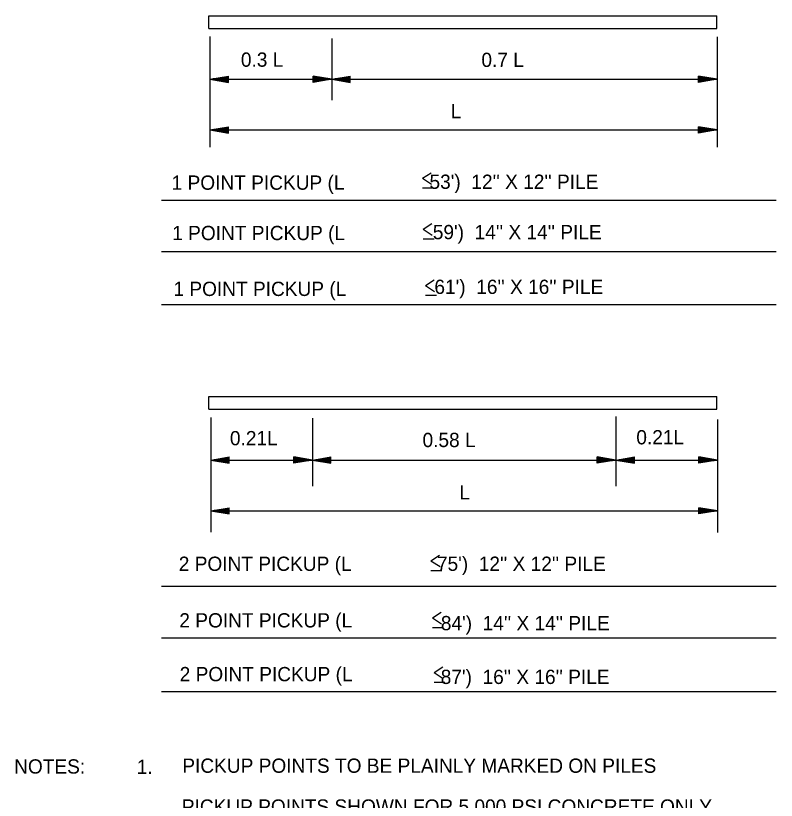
# Model space of a CAD drawing. Extents: x 22369.62 to 22373.29, y 22369.62 to 22372.46.
# Drawn here: x 22372.212 to 22372.836, y 22371.084 to 22371.728 of the extents above; entities that cross this region are included whole.
import ezdxf

# ---------------------------------------------------------------- set-up
doc = ezdxf.new("R2010")
doc.units = 0
for name, color, linetype in [('Level 10', 7, 'Continuous'), ('Level 4', 7, 'Continuous'), ('Level 7', 7, 'Continuous'), ('S-ANNO-DIMS', 7, 'Continuous')]:
    doc.layers.add(name, color=color, linetype=linetype)

msp = doc.modelspace()

# ---------------------------------------------------------------- linework, layer by layer
at = {"layer": 'Level 10'}
for p, q in [((22372.33178, 22371.57674), (22372.83582, 22371.57674)), ((22372.33178, 22371.53446), (22372.83582, 22371.53446)), ((22372.33178, 22371.49102), (22372.83582, 22371.49102)), ((22372.33178, 22371.25995), (22372.83582, 22371.25995)), ((22372.33178, 22371.21767), (22372.83582, 22371.21767)), ((22372.33178, 22371.17358), (22372.83582, 22371.17358))]:
    msp.add_line(p, q, dxfattribs=at)
at = {"layer": 'Level 7'}
for p, q in [((22372.37062, 22371.72793), (22372.78712, 22371.72793)), ((22372.37062, 22371.71751), (22372.37062, 22371.72793)), ((22372.78712, 22371.71751), (22372.78712, 22371.72793)), ((22372.37062, 22371.71751), (22372.78712, 22371.71751)), ((22372.37062, 22371.41555), (22372.78712, 22371.41555)), ((22372.37062, 22371.40513), (22372.37062, 22371.41555)), ((22372.78712, 22371.40513), (22372.78712, 22371.41555)), ((22372.37062, 22371.40513), (22372.78712, 22371.40513))]:
    msp.add_line(p, q, dxfattribs=at)
at = {"layer": 'S-ANNO-DIMS'}
for p, q in [((22372.37145, 22371.71092), (22372.37145, 22371.61999)), ((22372.47141, 22371.70935), (22372.47141, 22371.65875)), ((22372.7873, 22371.71066), (22372.7873, 22371.62012)), ((22372.37145, 22371.67586), (22372.38668, 22371.67845)), ((22372.37145, 22371.67586), (22372.7873, 22371.67586)), ((22372.37145, 22371.67586), (22372.38668, 22371.67586)), ((22372.37145, 22371.67586), (22372.38668, 22371.67327)), ((22372.37424, 22371.67607), (22372.38602, 22371.67807)), ((22372.38637, 22371.67622), (22372.37424, 22371.67607)), ((22372.38637, 22371.67549), (22372.37424, 22371.67563)), ((22372.37424, 22371.67563), (22372.38602, 22371.67364)), ((22372.37759, 22371.67638), (22372.38566, 22371.67772)), ((22372.386, 22371.67653), (22372.37759, 22371.67638)), ((22372.37759, 22371.67532), (22372.38566, 22371.67399)), ((22372.386, 22371.67518), (22372.37759, 22371.67532)), ((22372.38084, 22371.67666), (22372.38535, 22371.67734)), ((22372.38565, 22371.67681), (22372.38084, 22371.67666)), ((22372.38084, 22371.67505), (22372.38535, 22371.67436)), ((22372.38565, 22371.67491), (22372.38084, 22371.67505)), ((22372.38535, 22371.67699), (22372.38394, 22371.67693)), ((22372.38535, 22371.67734), (22372.38535, 22371.67699)), ((22372.38566, 22371.67772), (22372.38565, 22371.67681)), ((22372.38602, 22371.67807), (22372.386, 22371.67653)), ((22372.38602, 22371.67364), (22372.386, 22371.67518)), ((22372.38635, 22371.67807), (22372.38637, 22371.67622)), ((22372.38635, 22371.67364), (22372.38637, 22371.67549)), ((22372.38668, 22371.67327), (22372.38668, 22371.67845)), ((22372.45617, 22371.67327), (22372.45617, 22371.67845)), ((22372.47141, 22371.67586), (22372.45617, 22371.67845)), ((22372.47141, 22371.67586), (22372.45617, 22371.67586)), ((22372.47141, 22371.67586), (22372.45617, 22371.67327)), ((22372.45649, 22371.67807), (22372.45649, 22371.67622)), ((22372.45649, 22371.67622), (22372.46862, 22371.67607)), ((22372.45649, 22371.67549), (22372.46862, 22371.67563)), ((22372.45649, 22371.67364), (22372.45649, 22371.67549)), ((22372.46862, 22371.67607), (22372.45684, 22371.67807)), ((22372.45684, 22371.67807), (22372.45686, 22371.67653)), ((22372.46862, 22371.67563), (22372.45684, 22371.67364)), ((22372.45684, 22371.67364), (22372.45686, 22371.67518)), ((22372.45686, 22371.67653), (22372.46527, 22371.67638)), ((22372.45686, 22371.67518), (22372.46527, 22371.67532)), ((22372.46527, 22371.67638), (22372.4572, 22371.67772)), ((22372.4572, 22371.67772), (22372.4572, 22371.67681)), ((22372.4572, 22371.67681), (22372.46203, 22371.67666)), ((22372.46527, 22371.67532), (22372.4572, 22371.67399)), ((22372.4572, 22371.67491), (22372.46203, 22371.67505)), ((22372.45752, 22371.67734), (22372.4575, 22371.67699)), ((22372.4575, 22371.67699), (22372.4589, 22371.67693)), ((22372.46203, 22371.67666), (22372.45752, 22371.67734)), ((22372.46203, 22371.67505), (22372.45752, 22371.67436)), ((22372.47141, 22371.67586), (22372.48664, 22371.67845)), ((22372.47141, 22371.67586), (22372.48664, 22371.67586)), ((22372.47141, 22371.67586), (22372.48664, 22371.67327)), ((22372.4742, 22371.67607), (22372.48597, 22371.67807)), ((22372.48633, 22371.67622), (22372.4742, 22371.67607)), ((22372.48633, 22371.67549), (22372.4742, 22371.67563)), ((22372.4742, 22371.67563), (22372.48597, 22371.67364)), ((22372.47755, 22371.67638), (22372.48562, 22371.67772)), ((22372.48596, 22371.67653), (22372.47755, 22371.67638)), ((22372.47755, 22371.67532), (22372.48562, 22371.67399)), ((22372.48596, 22371.67518), (22372.47755, 22371.67532)), ((22372.4808, 22371.67666), (22372.48531, 22371.67734)), ((22372.48561, 22371.67681), (22372.4808, 22371.67666)), ((22372.4808, 22371.67505), (22372.48531, 22371.67436)), ((22372.48561, 22371.67491), (22372.4808, 22371.67505)), ((22372.48531, 22371.67699), (22372.48391, 22371.67693)), ((22372.48531, 22371.67734), (22372.48531, 22371.67699)), ((22372.48562, 22371.67772), (22372.48561, 22371.67681)), ((22372.48597, 22371.67807), (22372.48596, 22371.67653)), ((22372.48597, 22371.67364), (22372.48596, 22371.67518)), ((22372.48631, 22371.67807), (22372.48633, 22371.67622)), ((22372.48631, 22371.67364), (22372.48633, 22371.67549)), ((22372.48664, 22371.67327), (22372.48664, 22371.67845)), ((22372.77206, 22371.67327), (22372.77206, 22371.67845)), ((22372.7873, 22371.67586), (22372.77206, 22371.67845)), ((22372.7873, 22371.67586), (22372.77206, 22371.67586)), ((22372.7873, 22371.67586), (22372.77206, 22371.67327)), ((22372.77239, 22371.67807), (22372.77237, 22371.67622)), ((22372.77237, 22371.67622), (22372.7845, 22371.67607)), ((22372.77237, 22371.67549), (22372.7845, 22371.67563)), ((22372.77239, 22371.67364), (22372.77237, 22371.67549)), ((22372.7845, 22371.67607), (22372.77272, 22371.67807)), ((22372.77272, 22371.67807), (22372.77273, 22371.67653)), ((22372.7845, 22371.67563), (22372.77272, 22371.67364)), ((22372.77272, 22371.67364), (22372.77273, 22371.67518)), ((22372.77273, 22371.67653), (22372.78114, 22371.67638)), ((22372.77273, 22371.67518), (22372.78114, 22371.67532)), ((22372.78114, 22371.67638), (22372.77308, 22371.67772)), ((22372.77308, 22371.67772), (22372.77309, 22371.67681)), ((22372.78114, 22371.67532), (22372.77308, 22371.67399)), ((22372.77309, 22371.67681), (22372.7779, 22371.67666)), ((22372.77309, 22371.67491), (22372.7779, 22371.67505)), ((22372.7734, 22371.67734), (22372.77339, 22371.67699)), ((22372.77339, 22371.67699), (22372.77479, 22371.67693)), ((22372.7779, 22371.67666), (22372.7734, 22371.67734)), ((22372.7779, 22371.67505), (22372.7734, 22371.67436)), ((22372.38535, 22371.67472), (22372.38394, 22371.67478)), ((22372.38535, 22371.67436), (22372.38535, 22371.67472)), ((22372.38566, 22371.67399), (22372.38565, 22371.67491)), ((22372.4572, 22371.67399), (22372.4572, 22371.67491)), ((22372.4575, 22371.67472), (22372.4589, 22371.67478)), ((22372.45752, 22371.67436), (22372.4575, 22371.67472)), ((22372.48531, 22371.67472), (22372.48391, 22371.67478)), ((22372.48531, 22371.67436), (22372.48531, 22371.67472)), ((22372.48562, 22371.67399), (22372.48561, 22371.67491)), ((22372.77308, 22371.67399), (22372.77309, 22371.67491)), ((22372.77339, 22371.67472), (22372.77479, 22371.67478)), ((22372.7734, 22371.67436), (22372.77339, 22371.67472)), ((22372.37145, 22371.63421), (22372.38668, 22371.63679)), ((22372.37424, 22371.63443), (22372.38602, 22371.63642)), ((22372.38602, 22371.63642), (22372.386, 22371.63488)), ((22372.38635, 22371.63642), (22372.38637, 22371.63457)), ((22372.38668, 22371.63162), (22372.38668, 22371.63679)), ((22372.77206, 22371.63162), (22372.77206, 22371.63679)), ((22372.7873, 22371.63421), (22372.77206, 22371.63679)), ((22372.77239, 22371.63642), (22372.77237, 22371.63457)), ((22372.7845, 22371.63443), (22372.77272, 22371.63642)), ((22372.77272, 22371.63642), (22372.77273, 22371.63488)), ((22372.37145, 22371.63421), (22372.7873, 22371.63421)), ((22372.37145, 22371.63421), (22372.38668, 22371.63421)), ((22372.37145, 22371.63421), (22372.38668, 22371.63162)), ((22372.38637, 22371.63457), (22372.37424, 22371.63443)), ((22372.38637, 22371.63384), (22372.37424, 22371.63399)), ((22372.37424, 22371.63399), (22372.38602, 22371.632)), ((22372.37759, 22371.63474), (22372.38566, 22371.63607)), ((22372.386, 22371.63488), (22372.37759, 22371.63474)), ((22372.37759, 22371.63368), (22372.38566, 22371.63234)), ((22372.386, 22371.63353), (22372.37759, 22371.63368)), ((22372.38084, 22371.63501), (22372.38535, 22371.6357)), ((22372.38565, 22371.63516), (22372.38084, 22371.63501)), ((22372.38084, 22371.63341), (22372.38535, 22371.63272)), ((22372.38565, 22371.63325), (22372.38084, 22371.63341)), ((22372.38535, 22371.63534), (22372.38394, 22371.63528)), ((22372.38535, 22371.63307), (22372.38394, 22371.63313)), ((22372.38535, 22371.6357), (22372.38535, 22371.63534)), ((22372.38535, 22371.63272), (22372.38535, 22371.63307)), ((22372.38566, 22371.63607), (22372.38565, 22371.63516)), ((22372.38566, 22371.63234), (22372.38565, 22371.63325)), ((22372.38602, 22371.632), (22372.386, 22371.63353)), ((22372.38635, 22371.632), (22372.38637, 22371.63384)), ((22372.7873, 22371.63421), (22372.77206, 22371.63421)), ((22372.7873, 22371.63421), (22372.77206, 22371.63162)), ((22372.77237, 22371.63457), (22372.7845, 22371.63443)), ((22372.77237, 22371.63384), (22372.7845, 22371.63399)), ((22372.77239, 22371.632), (22372.77237, 22371.63384)), ((22372.7845, 22371.63399), (22372.77272, 22371.632)), ((22372.77272, 22371.632), (22372.77273, 22371.63353)), ((22372.77273, 22371.63488), (22372.78114, 22371.63474)), ((22372.77273, 22371.63353), (22372.78114, 22371.63368)), ((22372.78114, 22371.63474), (22372.77308, 22371.63607)), ((22372.77308, 22371.63607), (22372.77309, 22371.63516)), ((22372.78114, 22371.63368), (22372.77308, 22371.63234)), ((22372.77308, 22371.63234), (22372.77309, 22371.63325)), ((22372.77309, 22371.63516), (22372.7779, 22371.63501)), ((22372.77309, 22371.63325), (22372.7779, 22371.63341)), ((22372.7734, 22371.6357), (22372.77339, 22371.63534)), ((22372.77339, 22371.63534), (22372.77479, 22371.63528)), ((22372.77339, 22371.63307), (22372.77479, 22371.63313)), ((22372.7734, 22371.63272), (22372.77339, 22371.63307)), ((22372.7779, 22371.63501), (22372.7734, 22371.6357)), ((22372.7779, 22371.63341), (22372.7734, 22371.63272)), ((22372.5458, 22371.59454), (22372.55288, 22371.59914)), ((22372.5458, 22371.59454), (22372.55322, 22371.58972)), ((22372.5458, 22371.58663), (22372.55466, 22371.58663)), ((22372.54643, 22371.5528), (22372.55352, 22371.5574)), ((22372.54643, 22371.5528), (22372.55385, 22371.54798)), ((22372.54643, 22371.5449), (22372.55529, 22371.5449)), ((22372.54833, 22371.50664), (22372.55541, 22371.51124)), ((22372.54833, 22371.50664), (22372.55574, 22371.50182)), ((22372.54833, 22371.49873), (22372.55719, 22371.49873)), ((22372.37221, 22371.39844), (22372.37221, 22371.30436)), ((22372.70424, 22371.39932), (22372.70424, 22371.3421)), ((22372.45552, 22371.39782), (22372.45552, 22371.34217)), ((22372.78755, 22371.39673), (22372.78755, 22371.30403)), ((22372.37221, 22371.36349), (22372.38745, 22371.36607)), ((22372.38745, 22371.36089), (22372.38745, 22371.36607)), ((22372.44028, 22371.36089), (22372.44028, 22371.36607)), ((22372.45552, 22371.36349), (22372.44028, 22371.36607)), ((22372.45552, 22371.36349), (22372.47075, 22371.36607)), ((22372.47075, 22371.36089), (22372.47075, 22371.36607)), ((22372.68902, 22371.36089), (22372.68902, 22371.36607)), ((22372.70424, 22371.36349), (22372.68902, 22371.36607)), ((22372.70424, 22371.36349), (22372.71948, 22371.36607)), ((22372.71948, 22371.36089), (22372.71948, 22371.36607)), ((22372.77232, 22371.36089), (22372.77232, 22371.36607)), ((22372.78755, 22371.36349), (22372.77232, 22371.36607)), ((22372.37221, 22371.36349), (22372.78755, 22371.36349)), ((22372.37221, 22371.36349), (22372.38745, 22371.36349)), ((22372.37221, 22371.36349), (22372.38745, 22371.36089)), ((22372.375, 22371.3637), (22372.38679, 22371.3657)), ((22372.38713, 22371.36384), (22372.375, 22371.3637)), ((22372.38713, 22371.36311), (22372.375, 22371.36326)), ((22372.375, 22371.36326), (22372.38679, 22371.36127)), ((22372.37836, 22371.36401), (22372.38643, 22371.36534)), ((22372.38677, 22371.36416), (22372.37836, 22371.36401)), ((22372.37836, 22371.36295), (22372.38643, 22371.36161)), ((22372.38677, 22371.3628), (22372.37836, 22371.36295)), ((22372.3816, 22371.36428), (22372.38611, 22371.36497)), ((22372.38642, 22371.36444), (22372.3816, 22371.36428)), ((22372.3816, 22371.36268), (22372.38611, 22371.36199)), ((22372.38642, 22371.36253), (22372.3816, 22371.36268)), ((22372.38612, 22371.36461), (22372.38472, 22371.36455)), ((22372.38612, 22371.36234), (22372.38472, 22371.36241)), ((22372.38611, 22371.36497), (22372.38612, 22371.36461)), ((22372.38611, 22371.36199), (22372.38612, 22371.36234)), ((22372.38643, 22371.36534), (22372.38642, 22371.36444)), ((22372.38643, 22371.36161), (22372.38642, 22371.36253)), ((22372.38679, 22371.3657), (22372.38677, 22371.36416)), ((22372.38679, 22371.36127), (22372.38677, 22371.3628)), ((22372.38712, 22371.3657), (22372.38713, 22371.36384)), ((22372.38712, 22371.36127), (22372.38713, 22371.36311)), ((22372.45552, 22371.36349), (22372.44028, 22371.36349)), ((22372.45552, 22371.36349), (22372.44028, 22371.36089)), ((22372.44061, 22371.3657), (22372.4406, 22371.36384)), ((22372.4406, 22371.36384), (22372.45272, 22371.3637)), ((22372.4406, 22371.36311), (22372.45272, 22371.36326)), ((22372.44061, 22371.36127), (22372.4406, 22371.36311)), ((22372.45272, 22371.3637), (22372.44094, 22371.3657)), ((22372.44094, 22371.3657), (22372.44096, 22371.36416)), ((22372.45272, 22371.36326), (22372.44094, 22371.36127)), ((22372.44094, 22371.36127), (22372.44096, 22371.3628)), ((22372.44096, 22371.36416), (22372.44937, 22371.36401)), ((22372.44096, 22371.3628), (22372.44937, 22371.36295)), ((22372.44937, 22371.36401), (22372.44131, 22371.36534)), ((22372.44131, 22371.36534), (22372.44132, 22371.36444)), ((22372.44937, 22371.36295), (22372.44131, 22371.36161)), ((22372.44131, 22371.36161), (22372.44132, 22371.36253)), ((22372.44132, 22371.36444), (22372.44613, 22371.36428)), ((22372.44132, 22371.36253), (22372.44613, 22371.36268)), ((22372.44162, 22371.36497), (22372.44161, 22371.36461)), ((22372.44161, 22371.36461), (22372.44302, 22371.36455)), ((22372.44161, 22371.36234), (22372.44302, 22371.36241)), ((22372.44162, 22371.36199), (22372.44161, 22371.36234)), ((22372.44613, 22371.36428), (22372.44162, 22371.36497)), ((22372.44613, 22371.36268), (22372.44162, 22371.36199)), ((22372.45552, 22371.36349), (22372.47075, 22371.36349)), ((22372.45552, 22371.36349), (22372.47075, 22371.36089)), ((22372.45831, 22371.3637), (22372.47009, 22371.3657)), ((22372.47043, 22371.36384), (22372.45831, 22371.3637)), ((22372.47043, 22371.36311), (22372.45831, 22371.36326)), ((22372.45831, 22371.36326), (22372.47009, 22371.36127)), ((22372.46166, 22371.36401), (22372.46972, 22371.36534)), ((22372.47007, 22371.36416), (22372.46166, 22371.36401)), ((22372.46166, 22371.36295), (22372.46972, 22371.36161)), ((22372.47007, 22371.3628), (22372.46166, 22371.36295)), ((22372.4649, 22371.36428), (22372.46941, 22371.36497)), ((22372.46971, 22371.36444), (22372.4649, 22371.36428)), ((22372.4649, 22371.36268), (22372.46941, 22371.36199)), ((22372.46971, 22371.36253), (22372.4649, 22371.36268)), ((22372.46942, 22371.36461), (22372.46802, 22371.36455)), ((22372.46942, 22371.36234), (22372.46802, 22371.36241)), ((22372.46941, 22371.36497), (22372.46942, 22371.36461)), ((22372.46941, 22371.36199), (22372.46942, 22371.36234)), ((22372.46972, 22371.36534), (22372.46971, 22371.36444)), ((22372.46972, 22371.36161), (22372.46971, 22371.36253)), ((22372.47009, 22371.3657), (22372.47007, 22371.36416)), ((22372.47009, 22371.36127), (22372.47007, 22371.3628)), ((22372.47042, 22371.3657), (22372.47043, 22371.36384)), ((22372.47042, 22371.36127), (22372.47043, 22371.36311)), ((22372.70424, 22371.36349), (22372.68902, 22371.36349)), ((22372.70424, 22371.36349), (22372.68902, 22371.36089)), ((22372.68934, 22371.3657), (22372.68932, 22371.36384)), ((22372.68932, 22371.36384), (22372.70146, 22371.3637)), ((22372.68932, 22371.36311), (22372.70146, 22371.36326)), ((22372.68934, 22371.36127), (22372.68932, 22371.36311)), ((22372.70146, 22371.3637), (22372.68968, 22371.3657)), ((22372.68968, 22371.3657), (22372.68969, 22371.36416)), ((22372.70146, 22371.36326), (22372.68968, 22371.36127)), ((22372.68968, 22371.36127), (22372.68969, 22371.3628)), ((22372.68969, 22371.36416), (22372.6981, 22371.36401)), ((22372.68969, 22371.3628), (22372.6981, 22371.36295)), ((22372.6981, 22371.36401), (22372.69004, 22371.36534)), ((22372.69004, 22371.36534), (22372.69005, 22371.36444)), ((22372.6981, 22371.36295), (22372.69004, 22371.36161)), ((22372.69004, 22371.36161), (22372.69005, 22371.36253)), ((22372.69005, 22371.36444), (22372.69485, 22371.36428)), ((22372.69005, 22371.36253), (22372.69485, 22371.36268)), ((22372.69485, 22371.36428), (22372.69035, 22371.36497)), ((22372.69035, 22371.36497), (22372.69035, 22371.36461)), ((22372.69035, 22371.36461), (22372.69174, 22371.36455)), ((22372.69485, 22371.36268), (22372.69035, 22371.36199)), ((22372.69035, 22371.36234), (22372.69174, 22371.36241)), ((22372.69035, 22371.36199), (22372.69035, 22371.36234)), ((22372.70424, 22371.36349), (22372.71948, 22371.36349)), ((22372.70424, 22371.36349), (22372.71948, 22371.36089)), ((22372.70704, 22371.3637), (22372.71882, 22371.3657)), ((22372.71917, 22371.36384), (22372.70704, 22371.3637)), ((22372.71917, 22371.36311), (22372.70704, 22371.36326)), ((22372.70704, 22371.36326), (22372.71882, 22371.36127)), ((22372.71039, 22371.36401), (22372.71846, 22371.36534)), ((22372.71881, 22371.36416), (22372.71039, 22371.36401)), ((22372.71039, 22371.36295), (22372.71846, 22371.36161)), ((22372.71881, 22371.3628), (22372.71039, 22371.36295)), ((22372.71364, 22371.36428), (22372.71814, 22371.36497)), ((22372.71845, 22371.36444), (22372.71364, 22371.36428)), ((22372.71364, 22371.36268), (22372.71814, 22371.36199)), ((22372.71845, 22371.36253), (22372.71364, 22371.36268)), ((22372.71814, 22371.36461), (22372.71674, 22371.36455)), ((22372.71814, 22371.36234), (22372.71674, 22371.36241)), ((22372.71814, 22371.36497), (22372.71814, 22371.36461)), ((22372.71814, 22371.36199), (22372.71814, 22371.36234)), ((22372.71846, 22371.36534), (22372.71845, 22371.36444)), ((22372.71846, 22371.36161), (22372.71845, 22371.36253)), ((22372.71882, 22371.3657), (22372.71881, 22371.36416)), ((22372.71882, 22371.36127), (22372.71881, 22371.3628)), ((22372.71915, 22371.3657), (22372.71917, 22371.36384)), ((22372.71915, 22371.36127), (22372.71917, 22371.36311)), ((22372.78755, 22371.36349), (22372.77232, 22371.36349)), ((22372.78755, 22371.36349), (22372.77232, 22371.36089)), ((22372.77264, 22371.3657), (22372.77262, 22371.36384)), ((22372.77262, 22371.36384), (22372.78475, 22371.3637)), ((22372.77262, 22371.36311), (22372.78475, 22371.36326)), ((22372.77264, 22371.36127), (22372.77262, 22371.36311)), ((22372.78475, 22371.3637), (22372.77298, 22371.3657)), ((22372.77298, 22371.3657), (22372.77298, 22371.36416)), ((22372.77298, 22371.36416), (22372.7814, 22371.36401)), ((22372.78475, 22371.36326), (22372.77298, 22371.36127)), ((22372.77298, 22371.3628), (22372.7814, 22371.36295)), ((22372.77298, 22371.36127), (22372.77298, 22371.3628)), ((22372.7814, 22371.36401), (22372.77334, 22371.36534)), ((22372.77334, 22371.36534), (22372.77335, 22371.36444)), ((22372.7814, 22371.36295), (22372.77334, 22371.36161)), ((22372.77334, 22371.36161), (22372.77335, 22371.36253)), ((22372.77335, 22371.36444), (22372.77815, 22371.36428)), ((22372.77335, 22371.36253), (22372.77815, 22371.36268)), ((22372.77815, 22371.36428), (22372.77365, 22371.36497)), ((22372.77365, 22371.36497), (22372.77365, 22371.36461)), ((22372.77365, 22371.36461), (22372.77505, 22371.36455)), ((22372.77815, 22371.36268), (22372.77365, 22371.36199)), ((22372.77365, 22371.36234), (22372.77505, 22371.36241)), ((22372.77365, 22371.36199), (22372.77365, 22371.36234)), ((22372.37221, 22371.32183), (22372.38745, 22371.32442)), ((22372.37221, 22371.32183), (22372.78755, 22371.32183)), ((22372.37221, 22371.32183), (22372.38745, 22371.32183)), ((22372.37221, 22371.32183), (22372.38745, 22371.31925)), ((22372.375, 22371.32205), (22372.38679, 22371.32404)), ((22372.38713, 22371.3222), (22372.375, 22371.32205)), ((22372.38713, 22371.32147), (22372.375, 22371.32161)), ((22372.375, 22371.32161), (22372.38679, 22371.31962)), ((22372.37836, 22371.32236), (22372.38643, 22371.3237)), ((22372.38677, 22371.32251), (22372.37836, 22371.32236)), ((22372.37836, 22371.3213), (22372.38643, 22371.31997)), ((22372.38677, 22371.32116), (22372.37836, 22371.3213)), ((22372.3816, 22371.32263), (22372.38611, 22371.32332)), ((22372.38642, 22371.32278), (22372.3816, 22371.32263)), ((22372.3816, 22371.32103), (22372.38611, 22371.32034)), ((22372.38642, 22371.32087), (22372.3816, 22371.32103)), ((22372.38612, 22371.32297), (22372.38472, 22371.32291)), ((22372.38611, 22371.32332), (22372.38612, 22371.32297)), ((22372.38643, 22371.3237), (22372.38642, 22371.32278)), ((22372.38679, 22371.32404), (22372.38677, 22371.32251)), ((22372.38679, 22371.31962), (22372.38677, 22371.32116)), ((22372.38712, 22371.32404), (22372.38713, 22371.3222)), ((22372.38712, 22371.31962), (22372.38713, 22371.32147)), ((22372.38745, 22371.31925), (22372.38745, 22371.32442)), ((22372.77232, 22371.31925), (22372.77232, 22371.32442)), ((22372.78755, 22371.32183), (22372.77232, 22371.32442)), ((22372.78755, 22371.32183), (22372.77232, 22371.32183)), ((22372.78755, 22371.32183), (22372.77232, 22371.31925)), ((22372.77264, 22371.32404), (22372.77262, 22371.3222)), ((22372.77262, 22371.3222), (22372.78475, 22371.32205)), ((22372.77262, 22371.32147), (22372.78475, 22371.32161)), ((22372.77264, 22371.31962), (22372.77262, 22371.32147)), ((22372.78475, 22371.32205), (22372.77298, 22371.32404)), ((22372.77298, 22371.32404), (22372.77298, 22371.32251)), ((22372.77298, 22371.32251), (22372.7814, 22371.32236)), ((22372.78475, 22371.32161), (22372.77298, 22371.31962)), ((22372.77298, 22371.32116), (22372.7814, 22371.3213)), ((22372.77298, 22371.31962), (22372.77298, 22371.32116)), ((22372.7814, 22371.32236), (22372.77334, 22371.3237)), ((22372.77334, 22371.3237), (22372.77335, 22371.32278)), ((22372.7814, 22371.3213), (22372.77334, 22371.31997)), ((22372.77335, 22371.32278), (22372.77815, 22371.32263)), ((22372.77335, 22371.32087), (22372.77815, 22371.32103)), ((22372.77815, 22371.32263), (22372.77365, 22371.32332)), ((22372.77365, 22371.32332), (22372.77365, 22371.32297)), ((22372.77365, 22371.32297), (22372.77505, 22371.32291)), ((22372.77815, 22371.32103), (22372.77365, 22371.32034)), ((22372.38612, 22371.3207), (22372.38472, 22371.32076)), ((22372.38611, 22371.32034), (22372.38612, 22371.3207)), ((22372.38643, 22371.31997), (22372.38642, 22371.32087)), ((22372.77334, 22371.31997), (22372.77335, 22371.32087)), ((22372.77365, 22371.3207), (22372.77505, 22371.32076)), ((22372.77365, 22371.32034), (22372.77365, 22371.3207)), ((22372.55276, 22371.28088), (22372.55984, 22371.28548)), ((22372.55276, 22371.28088), (22372.56017, 22371.27606)), ((22372.55276, 22371.27298), (22372.56162, 22371.27298)), ((22372.55402, 22371.23408), (22372.5611, 22371.23869)), ((22372.55402, 22371.23408), (22372.56144, 22371.22927)), ((22372.55402, 22371.22618), (22372.56288, 22371.22618)), ((22372.55529, 22371.18919), (22372.56237, 22371.19379)), ((22372.55529, 22371.18919), (22372.5627, 22371.18437)), ((22372.55529, 22371.18128), (22372.56415, 22371.18128))]:
    msp.add_line(p, q, dxfattribs=at)

# ---------------------------------------------------------------- texts
at = {"layer": 'Level 10'}
for s, p in [("  53')  12'' X 12'' PILE", (22372.54285, 22371.58591)), ('1 POINT PICKUP (L', (22372.34016, 22371.58518)), ('1 POINT PICKUP (L', (22372.34064, 22371.54386)), ("  59')  14'' X 14'' PILE", (22372.54555, 22371.54461)), ('1 POINT PICKUP (L', (22372.34165, 22371.49804)), ("  61')  16'' X 16'' PILE", (22372.54687, 22371.49972)), ('2 POINT PICKUP (L', (22372.34602, 22371.27258)), ("  75')  12'' X 12'' PILE", (22372.54895, 22371.27261)), ('2 POINT PICKUP (L', (22372.34648, 22371.2262)), ("  84')  14'' X 14'' PILE", (22372.55215, 22371.22391)), ('2 POINT PICKUP (L', (22372.34678, 22371.18208)), ("  87')  16'' X 16'' PILE", (22372.55204, 22371.17983))]:
    msp.add_text(s, height=0.0116979, dxfattribs=at).set_placement(p)
at = {"layer": 'Level 4'}
for s, height, p in [('0.3 L', 0.011698, (22372.39693, 22371.68605)), ('0.7 L', 0.011698, (22372.59409, 22371.68588)), ('L', 0.0117, (22372.56901, 22371.64374)), ('0.21L', 0.011698, (22372.38794, 22371.37559)), ('0.58 L', 0.011698, (22372.54583, 22371.37412)), ('0.21L', 0.011698, (22372.72108, 22371.37635)), ('L', 0.0117, (22372.57607, 22371.33119)), ('NOTES:', 0.011698, (22372.21106, 22371.10636)), ('1.', 0.011698, (22372.31153, 22371.10598)), ('PICKUP POINTS TO BE PLAINLY MARKED ON PILES', 0.0116979, (22372.34892, 22371.10699)), ('PICKUP POINTS SHOWN FOR 5,000 PSI CONCRETE ONLY', 0.0116979, (22372.34851, 22371.07346))]:
    msp.add_text(s, height=height, dxfattribs=at).set_placement(p)

doc.saveas('drawing.dxf')
